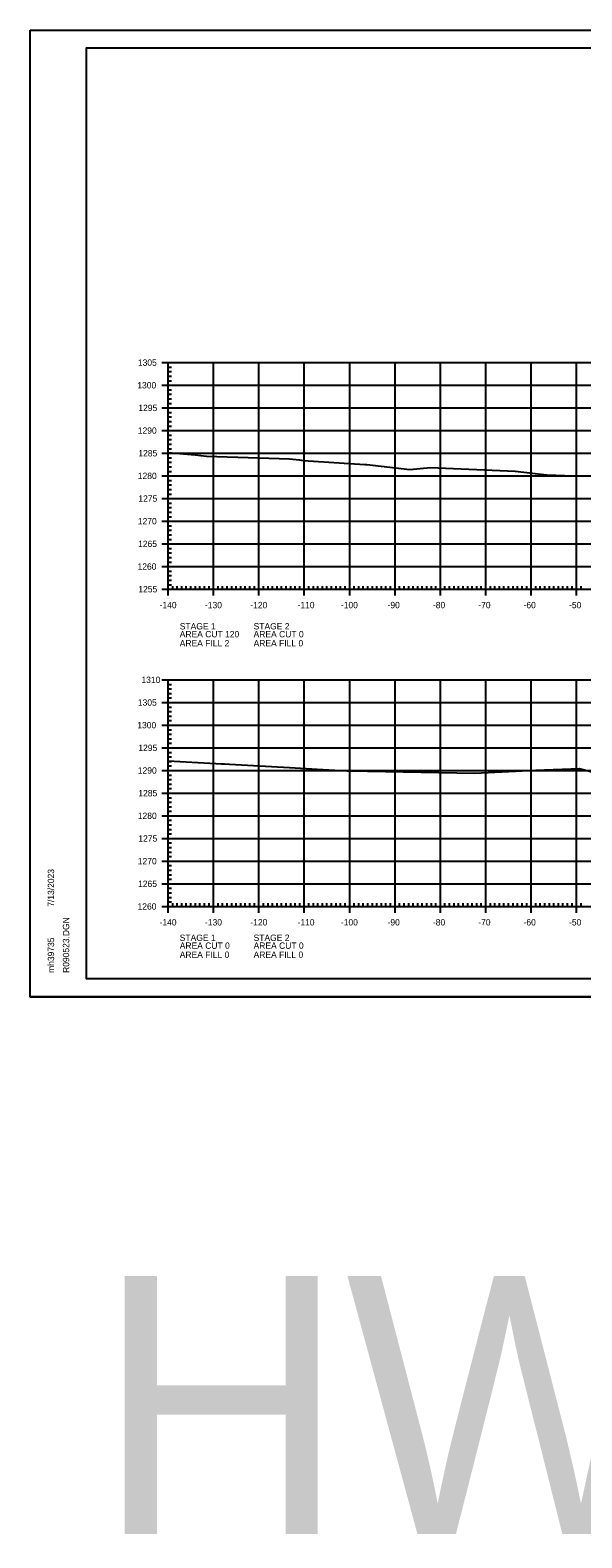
# Model space of a CAD drawing. Extents: x 1406028 to 1412453, y 321733 to 325986.
# Drawn here: x 1406419.5 to 1406541, y 321813.3 to 322146 of the extents above; entities that cross this region are included whole.
import ezdxf

# ---------------------------------------------------------------- set-up
doc = ezdxf.new("R2010")
doc.units = 0
for name, color, linetype in [('R_Axis', 7, 'Continuous'), ('R_Axis Annot', 7, 'Continuous'), ('R_Border', 7, 'Continuous'), ('R_Exist Surface', 7, 'Continuous'), ('R_Grid', 7, 'Continuous'), ('R_No Plot', 7, 'Continuous')]:
    doc.layers.add(name, color=color, linetype=linetype)

msp = doc.modelspace()

# ---------------------------------------------------------------- linework, layer by layer
at = {"layer": 'R_Axis'}
for p, q in [((1406448.48, 322072.65), (1406451.28, 322072.65)), ((1406449.88, 322022.65), (1406449.88, 322072.65)), ((1406449.88, 322071.65), (1406450.58, 322071.65)), ((1406449.88, 322070.65), (1406450.58, 322070.65)), ((1406448.48, 322067.65), (1406451.28, 322067.65)), ((1406449.88, 322069.65), (1406450.58, 322069.65)), ((1406449.88, 322068.65), (1406450.58, 322068.65)), ((1406449.88, 322066.65), (1406450.58, 322066.65)), ((1406449.88, 322065.65), (1406450.58, 322065.65)), ((1406449.88, 322064.65), (1406450.58, 322064.65)), ((1406449.88, 322063.65), (1406450.58, 322063.65)), ((1406448.48, 322062.65), (1406451.28, 322062.65)), ((1406449.88, 322061.65), (1406450.58, 322061.65)), ((1406449.88, 322060.65), (1406450.58, 322060.65)), ((1406448.48, 322057.65), (1406451.28, 322057.65)), ((1406449.88, 322059.65), (1406450.58, 322059.65)), ((1406449.88, 322058.65), (1406450.58, 322058.65)), ((1406449.88, 322056.65), (1406450.58, 322056.65)), ((1406449.88, 322055.65), (1406450.58, 322055.65)), ((1406449.88, 322054.65), (1406450.58, 322054.65)), ((1406449.88, 322053.65), (1406450.58, 322053.65)), ((1406448.48, 322052.65), (1406451.28, 322052.65)), ((1406449.88, 322051.65), (1406450.58, 322051.65)), ((1406449.88, 322050.65), (1406450.58, 322050.65)), ((1406448.48, 322047.65), (1406451.28, 322047.65)), ((1406449.88, 322049.65), (1406450.58, 322049.65)), ((1406449.88, 322048.65), (1406450.58, 322048.65)), ((1406449.88, 322046.65), (1406450.58, 322046.65)), ((1406449.88, 322045.65), (1406450.58, 322045.65)), ((1406449.88, 322044.65), (1406450.58, 322044.65)), ((1406449.88, 322043.65), (1406450.58, 322043.65)), ((1406448.48, 322042.65), (1406451.28, 322042.65)), ((1406449.88, 322041.65), (1406450.58, 322041.65)), ((1406449.88, 322040.65), (1406450.58, 322040.65)), ((1406448.48, 322037.65), (1406451.28, 322037.65)), ((1406449.88, 322039.65), (1406450.58, 322039.65)), ((1406449.88, 322038.65), (1406450.58, 322038.65)), ((1406449.88, 322036.65), (1406450.58, 322036.65)), ((1406449.88, 322035.65), (1406450.58, 322035.65)), ((1406449.88, 322034.65), (1406450.58, 322034.65)), ((1406449.88, 322033.65), (1406450.58, 322033.65)), ((1406448.48, 322032.65), (1406451.28, 322032.65)), ((1406449.88, 322031.65), (1406450.58, 322031.65)), ((1406449.88, 322030.65), (1406450.58, 322030.65)), ((1406448.48, 322027.65), (1406451.28, 322027.65)), ((1406449.88, 322029.65), (1406450.58, 322029.65)), ((1406449.88, 322028.65), (1406450.58, 322028.65)), ((1406449.88, 322026.65), (1406450.58, 322026.65)), ((1406449.88, 322025.65), (1406450.58, 322025.65)), ((1406449.88, 322024.65), (1406450.58, 322024.65)), ((1406449.88, 322021.25), (1406449.88, 322024.05)), ((1406449.88, 322023.65), (1406450.58, 322023.65)), ((1406459.88, 322021.25), (1406459.88, 322024.05)), ((1406469.88, 322021.25), (1406469.88, 322024.05)), ((1406479.88, 322021.25), (1406479.88, 322024.05)), ((1406489.88, 322021.25), (1406489.88, 322024.05)), ((1406499.88, 322021.25), (1406499.88, 322024.05)), ((1406509.88, 322021.25), (1406509.88, 322024.05)), ((1406519.88, 322021.25), (1406519.88, 322024.05)), ((1406529.88, 322021.25), (1406529.88, 322024.05)), ((1406539.88, 322021.25), (1406539.88, 322024.05)), ((1406448.48, 322022.65), (1406451.28, 322022.65)), ((1406449.88, 322022.65), (1406729.88, 322022.65)), ((1406450.88, 322022.65), (1406450.88, 322023.35)), ((1406451.88, 322022.65), (1406451.88, 322023.35)), ((1406452.88, 322022.65), (1406452.88, 322023.35)), ((1406453.88, 322022.65), (1406453.88, 322023.35)), ((1406454.88, 322022.65), (1406454.88, 322023.35)), ((1406455.88, 322022.65), (1406455.88, 322023.35)), ((1406456.88, 322022.65), (1406456.88, 322023.35)), ((1406457.88, 322022.65), (1406457.88, 322023.35)), ((1406458.88, 322022.65), (1406458.88, 322023.35)), ((1406460.88, 322022.65), (1406460.88, 322023.35)), ((1406461.88, 322022.65), (1406461.88, 322023.35)), ((1406462.88, 322022.65), (1406462.88, 322023.35)), ((1406463.88, 322022.65), (1406463.88, 322023.35)), ((1406464.88, 322022.65), (1406464.88, 322023.35)), ((1406465.88, 322022.65), (1406465.88, 322023.35)), ((1406466.88, 322022.65), (1406466.88, 322023.35)), ((1406467.88, 322022.65), (1406467.88, 322023.35)), ((1406468.88, 322022.65), (1406468.88, 322023.35)), ((1406470.88, 322022.65), (1406470.88, 322023.35)), ((1406471.88, 322022.65), (1406471.88, 322023.35)), ((1406472.88, 322022.65), (1406472.88, 322023.35)), ((1406473.88, 322022.65), (1406473.88, 322023.35)), ((1406474.88, 322022.65), (1406474.88, 322023.35)), ((1406475.88, 322022.65), (1406475.88, 322023.35)), ((1406476.88, 322022.65), (1406476.88, 322023.35)), ((1406477.88, 322022.65), (1406477.88, 322023.35)), ((1406478.88, 322022.65), (1406478.88, 322023.35)), ((1406480.88, 322022.65), (1406480.88, 322023.35)), ((1406481.88, 322022.65), (1406481.88, 322023.35)), ((1406482.88, 322022.65), (1406482.88, 322023.35)), ((1406483.88, 322022.65), (1406483.88, 322023.35)), ((1406484.88, 322022.65), (1406484.88, 322023.35)), ((1406485.88, 322022.65), (1406485.88, 322023.35)), ((1406486.88, 322022.65), (1406486.88, 322023.35)), ((1406487.88, 322022.65), (1406487.88, 322023.35)), ((1406488.88, 322022.65), (1406488.88, 322023.35)), ((1406490.88, 322022.65), (1406490.88, 322023.35)), ((1406491.88, 322022.65), (1406491.88, 322023.35)), ((1406492.88, 322022.65), (1406492.88, 322023.35)), ((1406493.88, 322022.65), (1406493.88, 322023.35)), ((1406494.88, 322022.65), (1406494.88, 322023.35)), ((1406495.88, 322022.65), (1406495.88, 322023.35)), ((1406496.88, 322022.65), (1406496.88, 322023.35)), ((1406497.88, 322022.65), (1406497.88, 322023.35)), ((1406498.88, 322022.65), (1406498.88, 322023.35)), ((1406500.88, 322022.65), (1406500.88, 322023.35)), ((1406501.88, 322022.65), (1406501.88, 322023.35)), ((1406502.88, 322022.65), (1406502.88, 322023.35)), ((1406503.88, 322022.65), (1406503.88, 322023.35)), ((1406504.88, 322022.65), (1406504.88, 322023.35)), ((1406505.88, 322022.65), (1406505.88, 322023.35)), ((1406506.88, 322022.65), (1406506.88, 322023.35)), ((1406507.88, 322022.65), (1406507.88, 322023.35)), ((1406508.88, 322022.65), (1406508.88, 322023.35)), ((1406510.88, 322022.65), (1406510.88, 322023.35)), ((1406511.88, 322022.65), (1406511.88, 322023.35)), ((1406512.88, 322022.65), (1406512.88, 322023.35)), ((1406513.88, 322022.65), (1406513.88, 322023.35)), ((1406514.88, 322022.65), (1406514.88, 322023.35)), ((1406515.88, 322022.65), (1406515.88, 322023.35)), ((1406516.88, 322022.65), (1406516.88, 322023.35)), ((1406517.88, 322022.65), (1406517.88, 322023.35)), ((1406518.88, 322022.65), (1406518.88, 322023.35)), ((1406520.88, 322022.65), (1406520.88, 322023.35)), ((1406521.88, 322022.65), (1406521.88, 322023.35)), ((1406522.88, 322022.65), (1406522.88, 322023.35)), ((1406523.88, 322022.65), (1406523.88, 322023.35)), ((1406524.88, 322022.65), (1406524.88, 322023.35)), ((1406525.88, 322022.65), (1406525.88, 322023.35)), ((1406526.88, 322022.65), (1406526.88, 322023.35)), ((1406527.88, 322022.65), (1406527.88, 322023.35)), ((1406528.88, 322022.65), (1406528.88, 322023.35)), ((1406530.88, 322022.65), (1406530.88, 322023.35)), ((1406531.88, 322022.65), (1406531.88, 322023.35)), ((1406532.88, 322022.65), (1406532.88, 322023.35)), ((1406533.88, 322022.65), (1406533.88, 322023.35)), ((1406534.88, 322022.65), (1406534.88, 322023.35)), ((1406535.88, 322022.65), (1406535.88, 322023.35)), ((1406536.88, 322022.65), (1406536.88, 322023.35)), ((1406537.88, 322022.65), (1406537.88, 322023.35)), ((1406538.88, 322022.65), (1406538.88, 322023.35)), ((1406540.88, 322022.65), (1406540.88, 322023.35)), ((1406448.48, 322002.65), (1406451.28, 322002.65)), ((1406449.88, 321952.65), (1406449.88, 322002.65)), ((1406449.88, 322001.65), (1406450.58, 322001.65)), ((1406449.88, 322000.65), (1406450.58, 322000.65)), ((1406448.48, 321997.65), (1406451.28, 321997.65)), ((1406449.88, 321999.65), (1406450.58, 321999.65)), ((1406449.88, 321998.65), (1406450.58, 321998.65)), ((1406449.88, 321996.65), (1406450.58, 321996.65)), ((1406449.88, 321995.65), (1406450.58, 321995.65)), ((1406449.88, 321994.65), (1406450.58, 321994.65)), ((1406449.88, 321993.65), (1406450.58, 321993.65)), ((1406448.48, 321992.65), (1406451.28, 321992.65)), ((1406449.88, 321991.65), (1406450.58, 321991.65)), ((1406449.88, 321990.65), (1406450.58, 321990.65)), ((1406448.48, 321987.65), (1406451.28, 321987.65)), ((1406449.88, 321989.65), (1406450.58, 321989.65)), ((1406449.88, 321988.65), (1406450.58, 321988.65)), ((1406449.88, 321986.65), (1406450.58, 321986.65)), ((1406449.88, 321985.65), (1406450.58, 321985.65)), ((1406449.88, 321984.65), (1406450.58, 321984.65)), ((1406449.88, 321983.65), (1406450.58, 321983.65)), ((1406448.48, 321982.65), (1406451.28, 321982.65)), ((1406449.88, 321981.65), (1406450.58, 321981.65)), ((1406449.88, 321980.65), (1406450.58, 321980.65)), ((1406448.48, 321977.65), (1406451.28, 321977.65)), ((1406449.88, 321979.65), (1406450.58, 321979.65)), ((1406449.88, 321978.65), (1406450.58, 321978.65)), ((1406449.88, 321976.65), (1406450.58, 321976.65)), ((1406449.88, 321975.65), (1406450.58, 321975.65)), ((1406449.88, 321974.65), (1406450.58, 321974.65)), ((1406449.88, 321973.65), (1406450.58, 321973.65)), ((1406448.48, 321972.65), (1406451.28, 321972.65)), ((1406449.88, 321971.65), (1406450.58, 321971.65)), ((1406449.88, 321970.65), (1406450.58, 321970.65)), ((1406448.48, 321967.65), (1406451.28, 321967.65)), ((1406449.88, 321969.65), (1406450.58, 321969.65)), ((1406449.88, 321968.65), (1406450.58, 321968.65)), ((1406449.88, 321966.65), (1406450.58, 321966.65)), ((1406449.88, 321965.65), (1406450.58, 321965.65)), ((1406449.88, 321964.65), (1406450.58, 321964.65)), ((1406449.88, 321963.65), (1406450.58, 321963.65)), ((1406448.48, 321962.65), (1406451.28, 321962.65)), ((1406449.88, 321961.65), (1406450.58, 321961.65)), ((1406449.88, 321960.65), (1406450.58, 321960.65)), ((1406448.48, 321957.65), (1406451.28, 321957.65)), ((1406449.88, 321959.65), (1406450.58, 321959.65)), ((1406449.88, 321958.65), (1406450.58, 321958.65)), ((1406449.88, 321956.65), (1406450.58, 321956.65)), ((1406449.88, 321955.65), (1406450.58, 321955.65)), ((1406449.88, 321954.65), (1406450.58, 321954.65)), ((1406449.88, 321951.25), (1406449.88, 321954.05)), ((1406449.88, 321953.65), (1406450.58, 321953.65)), ((1406459.88, 321951.25), (1406459.88, 321954.05)), ((1406469.88, 321951.25), (1406469.88, 321954.05)), ((1406479.88, 321951.25), (1406479.88, 321954.05)), ((1406489.88, 321951.25), (1406489.88, 321954.05)), ((1406499.88, 321951.25), (1406499.88, 321954.05)), ((1406509.88, 321951.25), (1406509.88, 321954.05)), ((1406519.88, 321951.25), (1406519.88, 321954.05)), ((1406529.88, 321951.25), (1406529.88, 321954.05)), ((1406539.88, 321951.25), (1406539.88, 321954.05)), ((1406448.48, 321952.65), (1406451.28, 321952.65)), ((1406449.88, 321952.65), (1406729.88, 321952.65)), ((1406450.88, 321952.65), (1406450.88, 321953.35)), ((1406451.88, 321952.65), (1406451.88, 321953.35)), ((1406452.88, 321952.65), (1406452.88, 321953.35)), ((1406453.88, 321952.65), (1406453.88, 321953.35)), ((1406454.88, 321952.65), (1406454.88, 321953.35)), ((1406455.88, 321952.65), (1406455.88, 321953.35)), ((1406456.88, 321952.65), (1406456.88, 321953.35)), ((1406457.88, 321952.65), (1406457.88, 321953.35)), ((1406458.88, 321952.65), (1406458.88, 321953.35)), ((1406460.88, 321952.65), (1406460.88, 321953.35)), ((1406461.88, 321952.65), (1406461.88, 321953.35)), ((1406462.88, 321952.65), (1406462.88, 321953.35)), ((1406463.88, 321952.65), (1406463.88, 321953.35)), ((1406464.88, 321952.65), (1406464.88, 321953.35)), ((1406465.88, 321952.65), (1406465.88, 321953.35)), ((1406466.88, 321952.65), (1406466.88, 321953.35)), ((1406467.88, 321952.65), (1406467.88, 321953.35)), ((1406468.88, 321952.65), (1406468.88, 321953.35)), ((1406470.88, 321952.65), (1406470.88, 321953.35)), ((1406471.88, 321952.65), (1406471.88, 321953.35)), ((1406472.88, 321952.65), (1406472.88, 321953.35)), ((1406473.88, 321952.65), (1406473.88, 321953.35)), ((1406474.88, 321952.65), (1406474.88, 321953.35)), ((1406475.88, 321952.65), (1406475.88, 321953.35)), ((1406476.88, 321952.65), (1406476.88, 321953.35)), ((1406477.88, 321952.65), (1406477.88, 321953.35)), ((1406478.88, 321952.65), (1406478.88, 321953.35)), ((1406480.88, 321952.65), (1406480.88, 321953.35)), ((1406481.88, 321952.65), (1406481.88, 321953.35)), ((1406482.88, 321952.65), (1406482.88, 321953.35)), ((1406483.88, 321952.65), (1406483.88, 321953.35)), ((1406484.88, 321952.65), (1406484.88, 321953.35)), ((1406485.88, 321952.65), (1406485.88, 321953.35)), ((1406486.88, 321952.65), (1406486.88, 321953.35)), ((1406487.88, 321952.65), (1406487.88, 321953.35)), ((1406488.88, 321952.65), (1406488.88, 321953.35)), ((1406490.88, 321952.65), (1406490.88, 321953.35)), ((1406491.88, 321952.65), (1406491.88, 321953.35)), ((1406492.88, 321952.65), (1406492.88, 321953.35)), ((1406493.88, 321952.65), (1406493.88, 321953.35)), ((1406494.88, 321952.65), (1406494.88, 321953.35)), ((1406495.88, 321952.65), (1406495.88, 321953.35)), ((1406496.88, 321952.65), (1406496.88, 321953.35)), ((1406497.88, 321952.65), (1406497.88, 321953.35)), ((1406498.88, 321952.65), (1406498.88, 321953.35)), ((1406500.88, 321952.65), (1406500.88, 321953.35)), ((1406501.88, 321952.65), (1406501.88, 321953.35)), ((1406502.88, 321952.65), (1406502.88, 321953.35)), ((1406503.88, 321952.65), (1406503.88, 321953.35)), ((1406504.88, 321952.65), (1406504.88, 321953.35)), ((1406505.88, 321952.65), (1406505.88, 321953.35)), ((1406506.88, 321952.65), (1406506.88, 321953.35)), ((1406507.88, 321952.65), (1406507.88, 321953.35)), ((1406508.88, 321952.65), (1406508.88, 321953.35)), ((1406510.88, 321952.65), (1406510.88, 321953.35)), ((1406511.88, 321952.65), (1406511.88, 321953.35)), ((1406512.88, 321952.65), (1406512.88, 321953.35)), ((1406513.88, 321952.65), (1406513.88, 321953.35)), ((1406514.88, 321952.65), (1406514.88, 321953.35)), ((1406515.88, 321952.65), (1406515.88, 321953.35)), ((1406516.88, 321952.65), (1406516.88, 321953.35)), ((1406517.88, 321952.65), (1406517.88, 321953.35)), ((1406518.88, 321952.65), (1406518.88, 321953.35)), ((1406520.88, 321952.65), (1406520.88, 321953.35)), ((1406521.88, 321952.65), (1406521.88, 321953.35)), ((1406522.88, 321952.65), (1406522.88, 321953.35)), ((1406523.88, 321952.65), (1406523.88, 321953.35)), ((1406524.88, 321952.65), (1406524.88, 321953.35)), ((1406525.88, 321952.65), (1406525.88, 321953.35)), ((1406526.88, 321952.65), (1406526.88, 321953.35)), ((1406527.88, 321952.65), (1406527.88, 321953.35)), ((1406528.88, 321952.65), (1406528.88, 321953.35)), ((1406530.88, 321952.65), (1406530.88, 321953.35)), ((1406531.88, 321952.65), (1406531.88, 321953.35)), ((1406532.88, 321952.65), (1406532.88, 321953.35)), ((1406533.88, 321952.65), (1406533.88, 321953.35)), ((1406534.88, 321952.65), (1406534.88, 321953.35)), ((1406535.88, 321952.65), (1406535.88, 321953.35)), ((1406536.88, 321952.65), (1406536.88, 321953.35)), ((1406537.88, 321952.65), (1406537.88, 321953.35)), ((1406538.88, 321952.65), (1406538.88, 321953.35)), ((1406540.88, 321952.65), (1406540.88, 321953.35))]:
    msp.add_line(p, q, dxfattribs=at)
at = {"layer": 'R_Border'}
for p, q in [((1406431.88, 322142.11), (1406748.06, 322142.11)), ((1406431.88, 321936.65), (1406431.88, 322142.11)), ((1406431.88, 321936.65), (1406431.88, 321936.65)), ((1406748.06, 321936.65), (1406431.88, 321936.65))]:
    msp.add_line(p, q, dxfattribs=at)
at = {"layer": 'R_Exist Surface'}
for points in [[(1406449.88, 322052.84), (1406455.82, 322052.28), (1406458.35, 322052.04), (1406469.79, 322051.61), (1406476.63, 322051.4), (1406478.8, 322051.16), (1406479.62, 322051.08), (1406493.22, 322050.19), (1406493.38, 322050.19), (1406493.66, 322050.18), (1406503.14, 322049.04), (1406507.72, 322049.5), (1406526.32, 322048.69), (1406533.3, 322047.86), (1406541.16, 322047.58)], [(1406449.88, 321984.75), (1406460.4, 321984.22), (1406461.58, 321984.15), (1406462.3, 321984.08), (1406463.37, 321984.03), (1406476.63, 321983.29), (1406483.99, 321982.83), (1406489.27, 321982.58), (1406489.49, 321982.57), (1406489.53, 321982.57), (1406489.89, 321982.57), (1406517.4, 321982.06), (1406530.88, 321982.72), (1406540.53, 321983.09), (1406545.05, 321981.84)]]:
    msp.add_lwpolyline(points, dxfattribs=at)
at = {"layer": 'R_Grid'}
for p, q in [((1406449.88, 322072.65), (1406729.88, 322072.65)), ((1406449.88, 322022.65), (1406449.88, 322072.65)), ((1406459.88, 322022.65), (1406459.88, 322072.65)), ((1406469.88, 322022.65), (1406469.88, 322072.65)), ((1406479.88, 322022.65), (1406479.88, 322072.65)), ((1406489.88, 322022.65), (1406489.88, 322072.65)), ((1406499.88, 322022.65), (1406499.88, 322072.65)), ((1406509.88, 322022.65), (1406509.88, 322072.65)), ((1406519.88, 322022.65), (1406519.88, 322072.65)), ((1406529.88, 322022.65), (1406529.88, 322072.65)), ((1406539.88, 322022.65), (1406539.88, 322072.65)), ((1406449.88, 322067.65), (1406729.88, 322067.65)), ((1406449.88, 322062.65), (1406729.88, 322062.65)), ((1406449.88, 322057.65), (1406729.88, 322057.65)), ((1406449.88, 322052.65), (1406729.88, 322052.65)), ((1406449.88, 322047.65), (1406729.88, 322047.65)), ((1406449.88, 322042.65), (1406729.88, 322042.65)), ((1406449.88, 322037.65), (1406729.88, 322037.65)), ((1406449.88, 322032.65), (1406729.88, 322032.65)), ((1406449.88, 322027.65), (1406729.88, 322027.65)), ((1406449.88, 322022.65), (1406729.88, 322022.65)), ((1406449.88, 322002.65), (1406729.88, 322002.65)), ((1406449.88, 321952.65), (1406449.88, 322002.65)), ((1406459.88, 321952.65), (1406459.88, 322002.65)), ((1406469.88, 321952.65), (1406469.88, 322002.65)), ((1406479.88, 321952.65), (1406479.88, 322002.65)), ((1406489.88, 321952.65), (1406489.88, 322002.65)), ((1406499.88, 321952.65), (1406499.88, 322002.65)), ((1406509.88, 321952.65), (1406509.88, 322002.65)), ((1406519.88, 321952.65), (1406519.88, 322002.65)), ((1406529.88, 321952.65), (1406529.88, 322002.65)), ((1406539.88, 321952.65), (1406539.88, 322002.65)), ((1406449.88, 321997.65), (1406729.88, 321997.65)), ((1406449.88, 321992.65), (1406729.88, 321992.65)), ((1406449.88, 321987.65), (1406729.88, 321987.65)), ((1406449.88, 321982.65), (1406729.88, 321982.65)), ((1406449.88, 321977.65), (1406729.88, 321977.65)), ((1406449.88, 321972.65), (1406729.88, 321972.65)), ((1406449.88, 321967.65), (1406729.88, 321967.65)), ((1406449.88, 321962.65), (1406729.88, 321962.65)), ((1406449.88, 321957.65), (1406729.88, 321957.65)), ((1406449.88, 321952.65), (1406729.88, 321952.65))]:
    msp.add_line(p, q, dxfattribs=at)
at = {"layer": 'R_No Plot'}
for p, q in [((1406419.48, 322146.01), (1406752.82, 322146.01)), ((1406419.48, 321932.67), (1406752.82, 321932.67))]:
    msp.add_line(p, q, dxfattribs=at)
for points in [[(1406419.48, 322146.01), (1406752.82, 322146.01), (1406752.82, 321932.67), (1406419.48, 321932.67)], [(1406665.8, 322142.11), (1406685.42, 322142.11), (1406685.42, 322132.23), (1406701.54, 322132.23), (1406724.73, 322132.23), (1406724.73, 322107.9), (1406748.06, 322107.9), (1406748.06, 321936.65), (1406431.88, 321936.65), (1406431.88, 322142.11)]]:
    msp.add_lwpolyline(points, close=True, dxfattribs=at)

# ---------------------------------------------------------------- texts
at = {"layer": 'R_Axis Annot'}
for s, height, p in [('1305', 1.4, (1406443.2, 322071.95)), ('1300', 1.4, (1406443.08, 322066.95)), ('1295', 1.4, (1406443.31, 322061.95)), ('1290', 1.4, (1406443.19, 322056.95)), ('1285', 1.4, (1406443.31, 322051.95)), ('1280', 1.4, (1406443.19, 322046.95)), ('1275', 1.4, (1406443.31, 322041.95)), ('1270', 1.4, (1406443.19, 322036.95)), ('1265', 1.4, (1406443.25, 322031.95)), ('1260', 1.4, (1406443.13, 322026.95)), ('1255', 1.4, (1406443.31, 322021.95)), ('-140', 1.4, (1406447.99, 322018.45)), ('-130', 1.4, (1406457.99, 322018.45)), ('-120', 1.4, (1406467.99, 322018.45)), ('-110', 1.4, (1406478.39, 322018.45)), ('-100', 1.4, (1406487.94, 322018.45)), ('-90', 1.4, (1406498.22, 322018.45)), ('-80', 1.4, (1406508.22, 322018.45)), ('-70', 1.4, (1406518.22, 322018.45)), ('-60', 1.4, (1406528.19, 322018.45)), ('-50', 1.4, (1406538.22, 322018.45)), ('STAGE 1', 1.4, (1406452.43, 322013.77)), ('STAGE 2', 1.4, (1406468.71, 322013.77)), ('AREA CUT 120', 1.4, (1406452.43, 322012.03)), ('AREA FILL 2', 1.4, (1406452.43, 322010.03)), ('AREA CUT 0', 1.4, (1406468.71, 322012.03)), ('AREA FILL 0', 1.4, (1406468.71, 322010.03)), ('1310', 1.4, (1406443.99, 322001.95)), ('1305', 1.4, (1406443.2, 321996.95)), ('1300', 1.4, (1406443.08, 321991.95)), ('1295', 1.4, (1406443.31, 321986.95)), ('1290', 1.4, (1406443.19, 321981.95)), ('1285', 1.4, (1406443.31, 321976.95)), ('1280', 1.4, (1406443.19, 321971.95)), ('1275', 1.4, (1406443.31, 321966.95)), ('1270', 1.4, (1406443.19, 321961.95)), ('1265', 1.4, (1406443.25, 321956.95)), ('1260', 1.4, (1406443.13, 321951.95)), ('-140', 1.4, (1406447.99, 321948.45)), ('-130', 1.4, (1406457.99, 321948.45)), ('-120', 1.4, (1406467.99, 321948.45)), ('-110', 1.4, (1406478.39, 321948.45)), ('-100', 1.4, (1406487.94, 321948.45)), ('-90', 1.4, (1406498.22, 321948.45)), ('-80', 1.4, (1406508.22, 321948.45)), ('-70', 1.4, (1406518.22, 321948.45)), ('-60', 1.4, (1406528.19, 321948.45)), ('-50', 1.4, (1406538.22, 321948.45)), ('AREA CUT 0', 1.4, (1406452.43, 321943.3)), ('STAGE 1', 1.4, (1406452.43, 321945.04)), ('AREA CUT 0', 1.4, (1406468.71, 321943.3)), ('STAGE 2', 1.4, (1406468.71, 321945.04)), ('AREA FILL 0', 1.4, (1406452.43, 321941.3)), ('AREA FILL 0', 1.4, (1406468.71, 321941.3)), ('HWY. 23', 56.929, (1406434.08, 321814.14))]:
    msp.add_text(s, height=height, dxfattribs=at).set_placement(p)
at = {"layer": 'R_Border'}
for s, p in [('7/13/2023', (1406424.75, 321952.58)), ('R090523.DGN', (1406428.07, 321937.98)), ('mh39735', (1406424.75, 321937.98))]:
    msp.add_text(s, height=1.4, rotation=90, dxfattribs=at).set_placement(p)
at = {"layer": 'R_No Plot'}
for p in [(1406476.59, 322051.35), (1406493.34, 322050.14), (1406503.1, 322048.99), (1406533.26, 322047.81), (1406460.36, 321984.17), (1406489.49, 321982.52), (1406517.36, 321982.01), (1406540.49, 321983.04)]:
    msp.add_text('+', height=0.1, dxfattribs=at).set_placement(p)

doc.saveas('drawing.dxf')
